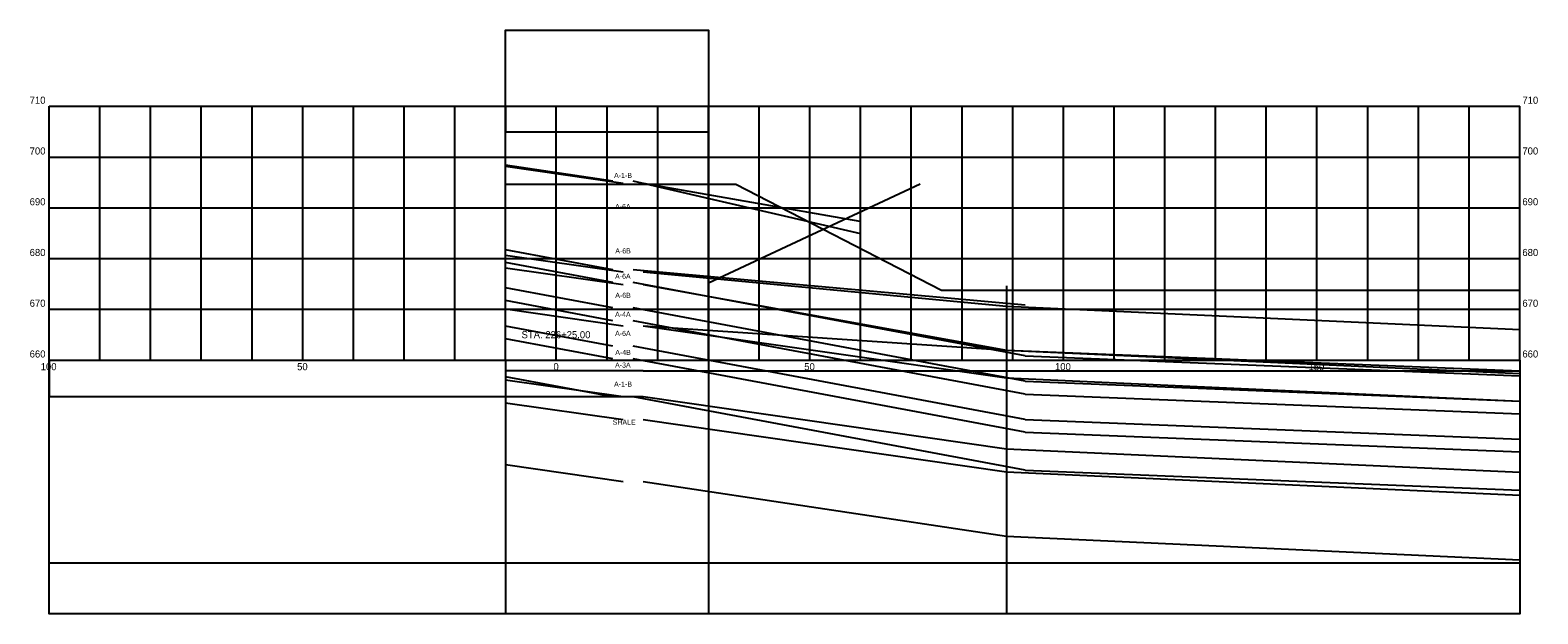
# Model space of a CAD drawing. Extents: x -104 to 194, y 610 to 725.
import ezdxf

# ---------------------------------------------------------------- set-up
doc = ezdxf.new("R2010")
doc.units = 0
for name, color, linetype in [('GT_Project_Cells', 7, 'Continuous'), ('GT_Project_Soil_Boring', 7, 'Continuous'), ('GT_Project_Soil_Layers', 7, 'Continuous')]:
    doc.layers.add(name, color=color, linetype=linetype)

msp = doc.modelspace()

# ---------------------------------------------------------------- linework, layer by layer
at = {"layer": 'GT_Project_Cells'}
for p, q in [((11.13, 695.26), (-10, 698.4)), ((-10, 698.2), (13.16, 694.87)), ((35.38, 694.57), (-10, 694.57)), ((60.02, 684.9), (15.13, 695.26)), ((17.16, 694.87), (59.86, 687.35)), ((11.13, 677.76), (-10, 681.71)), ((-10, 680.7), (13.16, 677.37)), ((11.13, 675.26), (-10, 679.21)), ((-10, 678.2), (13.16, 674.87)), ((92.45, 670.81), (15.13, 677.76)), ((92.45, 660.81), (15.13, 675.26)), ((17.16, 677.37), (88.77, 670.6)), ((11.13, 670.26), (-10, 674.21)), ((17.16, 674.87), (88.77, 661.96)), ((88.77, 674.6), (88.77, 610)), ((11.13, 667.76), (-10, 671.71)), ((-10, 670.1), (13.16, 666.77)), ((92.45, 655.81), (15.13, 670.26)), ((88.77, 670.6), (190, 666)), ((11.13, 662.76), (-10, 666.71)), ((92.45, 653.31), (15.13, 667.76)), ((17.16, 666.77), (88.77, 656.5)), ((17.16, 666.77), (88.77, 661.96)), ((11.13, 660.26), (-10, 664.21)), ((92.45, 648.31), (15.13, 662.76)), ((92.45, 645.81), (15.13, 660.26)), ((88.77, 661.96), (190, 657.36)), ((88.77, 661.96), (190, 657.87)), ((92.45, 660.81), (190, 656.91)), ((-10, 660), (-10, 610)), ((17.16, 657.87), (-10, 657.87)), ((17.16, 657.87), (190, 657.87)), ((11.13, 652.76), (-10, 656.71)), ((-10, 656.12), (13.16, 652.8)), ((88.77, 656.5), (190, 651.9)), ((92.45, 655.81), (190, 651.91)), ((-10, 651.6), (13.16, 648.27)), ((92.45, 638.28), (15.13, 652.76)), ((17.16, 652.8), (88.77, 642.53)), ((92.45, 653.31), (190, 649.41)), ((-10, 650), (-10, 620)), ((17.16, 648.27), (88.77, 638)), ((92.45, 648.31), (190, 644.41)), ((92.45, 645.81), (190, 641.91)), ((88.77, 642.53), (190, 637.93)), ((-10, 639.4), (13.16, 636.07)), ((88.77, 638), (190, 633.4)), ((92.45, 638.28), (190, 634.37)), ((17.16, 636.07), (88.77, 625.27)), ((88.77, 625.27), (190, 620.67))]:
    msp.add_line(p, q, dxfattribs=at)
for points in [[(-10, 710), (-10, 725), (30, 725), (30, 610)], [(-10, 710), (-10, 705), (22.54, 705)], [(-10, 705), (30, 705), (30, 685.14)], [(30, 705), (30, 675.21), (71.77, 694.74)], [(190, 673.73), (75.94, 673.73), (35.38, 694.57)], [(190, 660), (190, 610), (-100, 610), (-100, 660)], [(-100, 660), (-100, 652.8), (17.16, 652.8)], [(190, 650), (190, 620), (-100, 620), (-100, 650)]]:
    msp.add_lwpolyline(points, dxfattribs=at)
at = {"layer": 'GT_Project_Soil_Layers'}
for p, q in [((-100, 660), (-100, 710)), ((-100, 710), (190, 710)), ((-90, 660), (-90, 710)), ((-80, 660), (-80, 710)), ((-70, 660), (-70, 710)), ((-60, 660), (-60, 710)), ((-50, 660), (-50, 710)), ((-40, 660), (-40, 710)), ((-30, 660), (-30, 710)), ((-20, 660), (-20, 710)), ((-10, 660), (-10, 710)), ((0, 660), (0, 710)), ((10, 660), (10, 710)), ((20, 660), (20, 710)), ((30, 660), (30, 710)), ((40, 660), (40, 710)), ((50, 660), (50, 710)), ((60, 660), (60, 710)), ((70, 660), (70, 710)), ((80, 660), (80, 710)), ((90, 660), (90, 710)), ((100, 660), (100, 710)), ((110, 660), (110, 710)), ((120, 660), (120, 710)), ((130, 660), (130, 710)), ((140, 660), (140, 710)), ((150, 660), (150, 710)), ((160, 660), (160, 710)), ((170, 660), (170, 710)), ((180, 660), (180, 710)), ((190, 660), (190, 710)), ((-100, 700), (190, 700)), ((-100, 690), (190, 690)), ((-100, 680), (190, 680)), ((-100, 670), (190, 670)), ((-100, 660), (190, 660))]:
    msp.add_line(p, q, dxfattribs=at)

# ---------------------------------------------------------------- texts
at = {"layer": 'GT_Project_Cells'}
for s, p in [('A-1-B', (11.39, 695.88)), ('A-6A', (11.59, 689.76)), ('A-6B', (11.63, 681.01)), ('A-6A', (11.59, 676.01)), ('A-6B', (11.63, 672.26)), ('A-4A', (11.59, 668.51)), ('A-6A', (11.59, 664.76)), ('A-4B', (11.63, 661.01)), ('A-3A', (11.59, 658.51)), ('A-1-B', (11.39, 654.76)), ('SHALE', (11.12, 647.26))]:
    msp.add_text(s, height=1, dxfattribs=at).set_placement(p)
at = {"layer": 'GT_Project_Soil_Boring'}
for s, p in [('710', (-103.85, 710.5)), ('710', (190.5, 710.5)), ('700', (-103.85, 700.5)), ('700', (190.5, 700.5)), ('690', (-103.85, 690.5)), ('690', (190.5, 690.5)), ('680', (-103.85, 680.5)), ('680', (190.5, 680.5)), ('670', (-103.85, 670.5)), ('670', (190.5, 670.5)), ('STA. 226+25.00', (-6.85, 664.3)), ('660', (-103.85, 660.5)), ('660', (190.5, 660.5)), ('100', (-101.67, 658)), ('50', (-51.11, 658)), ('0', (-0.56, 658)), ('50', (48.89, 658)), ('100', (98.33, 658)), ('150', (148.33, 658))]:
    msp.add_text(s, height=1.4, dxfattribs=at).set_placement(p)

doc.saveas('drawing.dxf')
